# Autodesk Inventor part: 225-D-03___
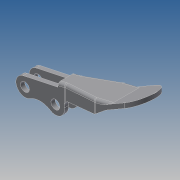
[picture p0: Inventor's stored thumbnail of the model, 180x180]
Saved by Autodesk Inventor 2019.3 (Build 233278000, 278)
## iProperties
Created: 2010-06
Part Number: 225-D-03___
Material: Ogólny
Document SubType Name: Modeling
Designer: CADENGINEERING4
Density: 1 g/cm^3
Appearance: Domyślna
Author: CADENGINEERING4
Revision Number: ANY
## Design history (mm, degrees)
feature "NONE"
sketch "Szkic3"
  geometry: L1 (9.5, -0.911)-(9.5, -9.628) reference; L2 (9.5, -0.911)-(9.514, 0) reference; L3 (2.99, 0)-(3.003, -0.662) reference; L4 (9.514, 0.007)-(2.99, 0.007) reference; L5 (3, -8.825)-(3, -0.691) reference; L6 (3, -19.993)-(9.5, -19.993); L7 (9.5, -19.993)-(9.5, 0.007); L8 (9.5, 0.007)-(3, 0.007); L9 (3, 0.007)-(3, -19.993); 1 further point
  constraints: 8 end point, 2 parallel, 1 collinear, 1 horizontal, 1 perpendicular, 1 point on line
  dimensions: "d0" = 20 distance between parallel lines of L6 L8; "d1" = 6.5 distance between parallel lines of L7 L9
extrude "Wyciągnięcie proste1" cut sketch "Szkic3" stored distance "d2" = 30; taper "d3" = 0 deg
node "Bryła1"
